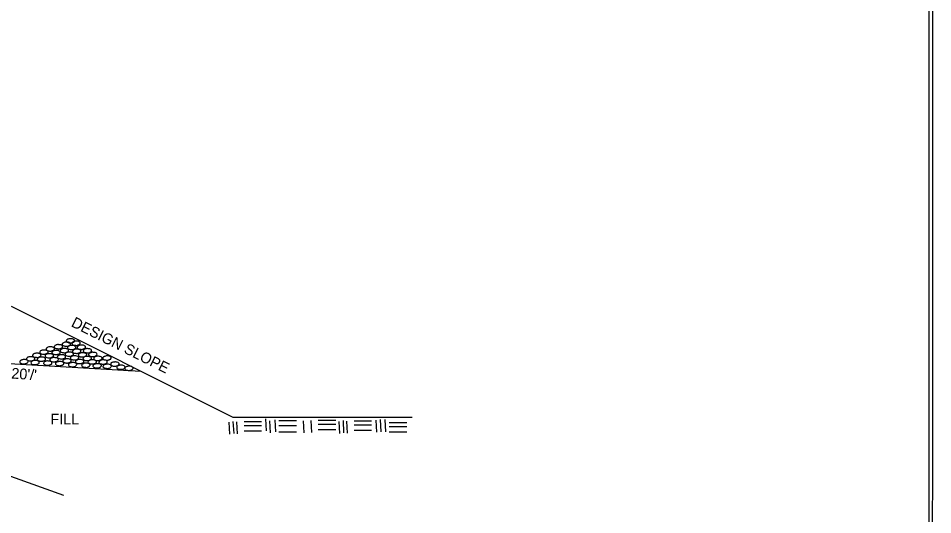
# Model space of a CAD drawing. Extents: x 714919 to 718439, y 1619644 to 1621844.
# Drawn here: x 717373 to 718397, y 1620734 to 1621289 of the extents above; entities that cross this region are included whole.
import ezdxf

# ---------------------------------------------------------------- set-up
doc = ezdxf.new("R2010")
doc.units = 0
for name, color, linetype in [('R_Annotation', 7, 'Continuous'), ('R_Border', 7, 'Continuous'), ('R_Draft', 7, 'Continuous'), ('R_No Plot', 7, 'Continuous')]:
    doc.layers.add(name, color=color, linetype=linetype)

msp = doc.modelspace()

# ---------------------------------------------------------------- linework, layer by layer
at = {"layer": 'R_Border'}
msp.add_line((718393.2, 1619722.5), (718393.1, 1621777.1), dxfattribs=at)
at = {"layer": 'R_Draft'}
for p, q in [((717614.2, 1620842.5), (717365.9, 1620966.6)), ((717203.1, 1620912.2), (717510.7, 1620894.2)), ((717076.3, 1620879.5), (717423.9, 1620755.7)), ((717814.4, 1620842.5), (717614.2, 1620842.5)), ((717650.2, 1620841), (717650.9, 1620827.5)), ((717660.5, 1620839.9), (717661.3, 1620826.4)), ((717701, 1620839.1), (717701.7, 1620825.6)), ((717728.8, 1620839.1), (717709.3, 1620839.1)), ((717737, 1620839), (717737.7, 1620825.4)), ((717773.9, 1620839.5), (717774.6, 1620825.9)), ((717778.7, 1620840), (717779.5, 1620826.5)), ((717783.8, 1620840), (717784.6, 1620826.5)), ((717609.2, 1620837.1), (717609.9, 1620823.6)), ((717613.8, 1620838.1), (717614.6, 1620824.5)), ((717617.9, 1620837.6), (717618.6, 1620824.1)), ((717645.7, 1620837.6), (717626.2, 1620837.6)), ((717645.7, 1620833.1), (717626.2, 1620833.1)), ((717654.8, 1620838.8), (717655.5, 1620825.2)), ((717685, 1620838.8), (717665.3, 1620838.8)), ((717685, 1620833), (717665.3, 1620833)), ((717692.3, 1620838.6), (717693, 1620825.1)), ((717728.8, 1620834.6), (717709.3, 1620834.6)), ((717732.3, 1620838), (717733.1, 1620824.5)), ((717741, 1620838.5), (717741.8, 1620824.9)), ((717768.9, 1620838.5), (717749.3, 1620838.5)), ((717768.9, 1620834), (717749.3, 1620834)), ((717808.4, 1620836.5), (717788.8, 1620836.5)), ((717808.4, 1620832), (717788.8, 1620832)), ((717645.7, 1620827.1), (717626.2, 1620827.1)), ((717685, 1620826.1), (717665.3, 1620826.1)), ((717728.8, 1620828.5), (717709.3, 1620828.5)), ((717768.9, 1620828), (717749.3, 1620828)), ((717808.4, 1620825.9), (717788.8, 1620825.9))]:
    msp.add_line(p, q, dxfattribs=at)
for points in [[(717409.4, 1620916.6), (717407.7, 1620916.8), (717405.7, 1620917.5), (717404.8, 1620918.3), (717404.6, 1620918.9), (717405.1, 1620919.9), (717405.7, 1620920.4), (717406.7, 1620921), (717408.3, 1620921.4), (717409.2, 1620921.4), (717410.4, 1620921.4), (717411.8, 1620921.2), (717412.9, 1620920.7), (717413.9, 1620919.8), (717414, 1620919.2), (717413.8, 1620918.3), (717413, 1620917.6), (717412.3, 1620917.4), (717411.1, 1620917), (717410.4, 1620916.7), (717409.4, 1620916.6)], [(717418.6, 1620919.2), (717416.9, 1620919.4), (717414.9, 1620920), (717413.9, 1620920.8), (717413.8, 1620921.5), (717414.3, 1620922.5), (717414.8, 1620923), (717415.9, 1620923.5), (717417.5, 1620923.9), (717418.4, 1620923.9), (717419.6, 1620923.8), (717421, 1620923.7), (717422, 1620923.3), (717423, 1620922.4), (717423.2, 1620921.8), (717422.9, 1620920.8), (717422.1, 1620920.2), (717421.4, 1620919.9), (717420.3, 1620919.5), (717419.6, 1620919.2), (717418.6, 1620919.2)], [(717427.4, 1620922), (717425.7, 1620922.2), (717423.7, 1620922.8), (717422.7, 1620923.7), (717422.6, 1620924.3), (717423.1, 1620925.2), (717423.7, 1620925.7), (717424.8, 1620926.3), (717426.3, 1620926.7), (717427.2, 1620926.7), (717428.4, 1620926.6), (717429.8, 1620926.5), (717430.9, 1620926.1), (717431.8, 1620925.2), (717432, 1620924.6), (717431.7, 1620923.6), (717431, 1620923.1), (717430.2, 1620922.7), (717429.1, 1620922.3), (717428.4, 1620922.1), (717427.4, 1620922)], [(717431.8, 1620925.7), (717430.2, 1620926), (717428.2, 1620926.5), (717427.3, 1620927.4), (717427.1, 1620928), (717427.6, 1620929), (717428.1, 1620929.5), (717429.2, 1620930.1), (717430.8, 1620930.5), (717431.7, 1620930.5), (717432.9, 1620930.4), (717434.3, 1620930.3), (717435.3, 1620929.8), (717436.4, 1620929), (717436.6, 1620928.2), (717436.3, 1620927.4), (717435.5, 1620926.7), (717434.7, 1620926.4), (717433.6, 1620926), (717432.9, 1620925.8), (717431.8, 1620925.7)], [(717433.3, 1620918.3), (717431.5, 1620918.5), (717429.6, 1620919), (717428.6, 1620920), (717428.4, 1620920.5), (717428.9, 1620921.5), (717429.5, 1620922), (717430.6, 1620922.6), (717432.2, 1620923), (717433, 1620923), (717434.3, 1620922.9), (717435.7, 1620922.8), (717436.7, 1620922.3), (717437.7, 1620921.5), (717437.9, 1620920.8), (717437.5, 1620919.9), (717436.8, 1620919.2), (717436.1, 1620919), (717435, 1620918.6), (717434.3, 1620918.3), (717433.3, 1620918.3)], [(717438.2, 1620923), (717436.6, 1620923.3), (717434.5, 1620923.7), (717433.6, 1620924.7), (717433.4, 1620925.2), (717433.9, 1620926.3), (717434.5, 1620926.7), (717435.6, 1620927.3), (717437.2, 1620927.8), (717438, 1620927.8), (717439.3, 1620927.6), (717440.7, 1620927.6), (717441.7, 1620927), (717442.7, 1620926.2), (717442.9, 1620925.5), (717442.5, 1620924.7), (717441.8, 1620924), (717441, 1620923.7), (717439.9, 1620923.3), (717439.3, 1620923.1), (717438.2, 1620923)], [(717444.2, 1620918.6), (717442.4, 1620918.8), (717440.5, 1620919.2), (717439.5, 1620920.3), (717439.3, 1620920.8), (717439.9, 1620921.8), (717440.4, 1620922.3), (717441.6, 1620922.9), (717443.2, 1620923.3), (717444, 1620923.3), (717445.2, 1620923.3), (717446.6, 1620923.2), (717447.7, 1620922.6), (717448.6, 1620921.8), (717448.8, 1620921.1), (717448.5, 1620920.2), (717447.7, 1620919.6), (717447, 1620919.2), (717445.9, 1620918.9), (717445.2, 1620918.7), (717444.2, 1620918.6)], [(717394.2, 1620909.6), (717392.5, 1620909.8), (717390.6, 1620910.3), (717389.6, 1620911.3), (717389.5, 1620911.8), (717389.9, 1620912.8), (717390.4, 1620913.3), (717391.5, 1620913.8), (717393.2, 1620914.3), (717394, 1620914.3), (717395.2, 1620914.2), (717396.6, 1620914.1), (717397.7, 1620913.6), (717398.7, 1620912.8), (717398.9, 1620912.1), (717398.6, 1620911.2), (717397.8, 1620910.6), (717397.1, 1620910.3), (717395.9, 1620909.8), (717395.2, 1620909.6), (717394.2, 1620909.6)], [(717402.2, 1620913.2), (717400.5, 1620913.3), (717398.5, 1620913.9), (717397.5, 1620914.8), (717397.4, 1620915.4), (717397.8, 1620916.4), (717398.5, 1620916.8), (717399.6, 1620917.5), (717401.2, 1620917.8), (717402, 1620917.8), (717403.2, 1620917.8), (717404.6, 1620917.6), (717405.7, 1620917.2), (717406.7, 1620916.3), (717406.8, 1620915.7), (717406.5, 1620914.7), (717405.7, 1620914.2), (717405, 1620913.8), (717404, 1620913.5), (717403.3, 1620913.3), (717402.2, 1620913.2)], [(717408.2, 1620909), (717406.5, 1620909.2), (717404.5, 1620909.8), (717403.6, 1620910.7), (717403.4, 1620911.3), (717403.9, 1620912.3), (717404.4, 1620912.8), (717405.6, 1620913.4), (717407.2, 1620913.7), (717408, 1620913.7), (717409.3, 1620913.7), (717410.6, 1620913.6), (717411.7, 1620913.1), (717412.7, 1620912.2), (717412.8, 1620911.6), (717412.5, 1620910.6), (717411.8, 1620910.1), (717411, 1620909.8), (717409.9, 1620909.3), (717409.3, 1620909.1), (717408.2, 1620909)], [(717415.8, 1620912.7), (717414.1, 1620912.9), (717412.2, 1620913.5), (717411.2, 1620914.4), (717411, 1620914.9), (717411.6, 1620916), (717412.1, 1620916.5), (717413.2, 1620917.1), (717414.8, 1620917.5), (717415.6, 1620917.5), (717416.9, 1620917.5), (717418.3, 1620917.3), (717419.3, 1620916.7), (717420.3, 1620915.9), (717420.5, 1620915.3), (717420.2, 1620914.4), (717419.4, 1620913.7), (717418.7, 1620913.4), (717417.5, 1620913.1), (717416.9, 1620912.8), (717415.8, 1620912.7)], [(717421.9, 1620907.8), (717420.2, 1620908), (717418.2, 1620908.6), (717417.2, 1620909.4), (717417.1, 1620910), (717417.6, 1620911), (717418.2, 1620911.6), (717419.2, 1620912.1), (717420.8, 1620912.5), (717421.6, 1620912.5), (717422.9, 1620912.5), (717424.3, 1620912.3), (717425.4, 1620911.8), (717426.4, 1620910.9), (717426.5, 1620910.4), (717426.2, 1620909.4), (717425.5, 1620908.8), (717424.7, 1620908.5), (717423.6, 1620908.1), (717422.9, 1620907.9), (717421.9, 1620907.8)], [(717425.3, 1620914.8), (717423.6, 1620915), (717421.5, 1620915.6), (717420.5, 1620916.5), (717420.4, 1620917.1), (717420.9, 1620918), (717421.5, 1620918.6), (717422.7, 1620919.2), (717424.2, 1620919.5), (717425, 1620919.5), (717426.3, 1620919.5), (717427.6, 1620919.3), (717428.8, 1620918.9), (717429.7, 1620918), (717429.8, 1620917.4), (717429.5, 1620916.4), (717428.8, 1620915.9), (717428.1, 1620915.5), (717427, 1620915.2), (717426.3, 1620914.9), (717425.3, 1620914.8)], [(717430.6, 1620910.9), (717428.9, 1620911), (717427, 1620911.6), (717426, 1620912.5), (717425.9, 1620913.1), (717426.3, 1620914.1), (717426.8, 1620914.6), (717428, 1620915.2), (717429.5, 1620915.6), (717430.4, 1620915.6), (717431.6, 1620915.5), (717433, 1620915.4), (717434.1, 1620914.9), (717435.1, 1620914), (717435.2, 1620913.4), (717435, 1620912.5), (717434.2, 1620911.9), (717433.5, 1620911.6), (717432.3, 1620911.1), (717431.6, 1620910.9), (717430.6, 1620910.9)], [(717436.4, 1620911.4), (717438, 1620911.4), (717440.1, 1620910.7), (717441, 1620909.8), (717441.2, 1620909.2), (717440.6, 1620908.2), (717440.1, 1620907.7), (717439, 1620907.2), (717437.4, 1620906.8), (717436.5, 1620906.7), (717435.3, 1620906.9), (717433.9, 1620907.1), (717432.9, 1620907.4), (717431.9, 1620908.3), (717431.7, 1620908.9), (717432, 1620909.8), (717432.8, 1620910.4), (717433.5, 1620910.9), (717434.6, 1620911.3), (717435.3, 1620911.4), (717436.4, 1620911.4)], [(717438.8, 1620914), (717437.2, 1620914.3), (717435.2, 1620914.7), (717434.2, 1620915.7), (717434.1, 1620916.3), (717434.6, 1620917.3), (717435.1, 1620917.7), (717436.3, 1620918.4), (717437.8, 1620918.8), (717438.7, 1620918.8), (717439.9, 1620918.7), (717441.3, 1620918.6), (717442.3, 1620918.1), (717443.4, 1620917.3), (717443.5, 1620916.6), (717443.2, 1620915.7), (717442.4, 1620915.1), (717441.7, 1620914.7), (717440.6, 1620914.4), (717439.9, 1620914.1), (717438.8, 1620914)], [(717445.2, 1620914.8), (717447, 1620914.7), (717449, 1620914.1), (717450, 1620913.2), (717450.1, 1620912.6), (717449.6, 1620911.6), (717449, 1620911.2), (717447.9, 1620910.5), (717446.3, 1620910.2), (717445.5, 1620910.2), (717444.2, 1620910.3), (717442.8, 1620910.3), (717441.8, 1620910.8), (717440.8, 1620911.7), (717440.7, 1620912.3), (717441, 1620913.2), (717441.8, 1620913.8), (717442.4, 1620914.2), (717443.6, 1620914.6), (717444.2, 1620914.8), (717445.2, 1620914.8)], [(717450.4, 1620910.8), (717452.1, 1620910.6), (717454.1, 1620910.1), (717455.2, 1620909.1), (717455.3, 1620908.5), (717454.8, 1620907.5), (717454.2, 1620907.1), (717453, 1620906.6), (717451.4, 1620906), (717450.6, 1620906), (717449.3, 1620906.2), (717448, 1620906.3), (717447, 1620906.8), (717446, 1620907.6), (717445.9, 1620908.2), (717446.2, 1620909.1), (717446.8, 1620909.8), (717447.5, 1620910.2), (717448.6, 1620910.6), (717449.4, 1620910.7), (717450.4, 1620910.8)], [(717450.8, 1620919.5), (717452.4, 1620919.2), (717454.4, 1620918.8), (717455.5, 1620917.8), (717455.6, 1620917.3), (717455.1, 1620916.2), (717454.5, 1620915.8), (717453.4, 1620915.1), (717451.8, 1620914.7), (717451, 1620914.7), (717449.8, 1620914.9), (717448.3, 1620915), (717447.3, 1620915.4), (717446.3, 1620916.3), (717446.2, 1620917), (717446.5, 1620917.8), (717447.2, 1620918.5), (717447.9, 1620918.9), (717449, 1620919.2), (717449.7, 1620919.4), (717450.8, 1620919.5)], [(717456.8, 1620915.3), (717458.5, 1620915.1), (717460.5, 1620914.6), (717461.5, 1620913.6), (717461.7, 1620913.1), (717461.1, 1620912), (717460.6, 1620911.6), (717459.4, 1620910.9), (717457.9, 1620910.6), (717457, 1620910.6), (717455.7, 1620910.6), (717454.3, 1620910.7), (717453.3, 1620911.3), (717452.3, 1620912.1), (717452.2, 1620912.8), (717452.5, 1620913.6), (717453.2, 1620914.3), (717454, 1620914.6), (717455.1, 1620915), (717455.7, 1620915.2), (717456.8, 1620915.3)], [(717462.5, 1620910.9), (717464.2, 1620910.7), (717466.1, 1620910.2), (717467.2, 1620909.3), (717467.3, 1620908.7), (717466.7, 1620907.7), (717466.2, 1620907.3), (717465.1, 1620906.7), (717463.5, 1620906.2), (717462.6, 1620906.2), (717461.4, 1620906.3), (717460, 1620906.4), (717458.9, 1620906.9), (717458, 1620907.8), (717457.9, 1620908.4), (717458.1, 1620909.3), (717458.9, 1620909.9), (717459.6, 1620910.3), (717460.7, 1620910.7), (717461.5, 1620910.9), (717462.5, 1620910.9)], [(717472.8, 1620906.6), (717471.1, 1620906.8), (717469.2, 1620907.3), (717468.2, 1620908.2), (717468.1, 1620908.8), (717468.6, 1620909.8), (717469.1, 1620910.3), (717470.2, 1620910.8), (717471.8, 1620911.3), (717472.7, 1620911.3), (717473.9, 1620911.2), (717475.3, 1620911.1), (717476.3, 1620910.6), (717477.3, 1620909.7), (717477.5, 1620909), (717477.2, 1620908.2), (717476.5, 1620907.5), (717475.7, 1620907.3), (717474.5, 1620906.8), (717473.9, 1620906.6), (717472.8, 1620906.6)], [(717379.8, 1620902.5), (717378.2, 1620902.6), (717376.3, 1620903.1), (717375.3, 1620904.1), (717375.1, 1620904.6), (717375.7, 1620905.7), (717376.1, 1620906.1), (717377.3, 1620906.8), (717378.9, 1620907.1), (717379.7, 1620907.1), (717381, 1620907.1), (717382.4, 1620907), (717383.5, 1620906.5), (717384.4, 1620905.6), (717384.6, 1620904.9), (717384.2, 1620904.1), (717383.6, 1620903.4), (717382.7, 1620903.1), (717381.6, 1620902.7), (717381, 1620902.5), (717379.8, 1620902.5)], [(717387.2, 1620905.7), (717385.5, 1620905.8), (717383.6, 1620906.4), (717382.6, 1620907.3), (717382.5, 1620907.9), (717383, 1620908.9), (717383.5, 1620909.4), (717384.6, 1620910), (717386.2, 1620910.4), (717387, 1620910.4), (717388.3, 1620910.3), (717389.7, 1620910.2), (717390.7, 1620909.7), (717391.8, 1620908.8), (717391.9, 1620908.2), (717391.6, 1620907.3), (717390.9, 1620906.7), (717390.1, 1620906.3), (717388.9, 1620905.9), (717388.3, 1620905.7), (717387.2, 1620905.7)], [(717392.3, 1620901.5), (717390.6, 1620901.6), (717388.6, 1620902.2), (717387.7, 1620903.1), (717387.5, 1620903.7), (717388.1, 1620904.7), (717388.5, 1620905.2), (717389.7, 1620905.8), (717391.3, 1620906.2), (717392.1, 1620906.2), (717393.4, 1620906.1), (717394.7, 1620906), (717395.8, 1620905.5), (717396.8, 1620904.6), (717397, 1620904), (717396.7, 1620903), (717395.9, 1620902.5), (717395.2, 1620902.1), (717394, 1620901.7), (717393.4, 1620901.5), (717392.3, 1620901.5)], [(717399.4, 1620905.3), (717397.7, 1620905.5), (717395.8, 1620906), (717394.8, 1620907), (717394.7, 1620907.5), (717395.2, 1620908.5), (717395.7, 1620909), (717396.8, 1620909.6), (717398.4, 1620910), (717399.2, 1620910), (717400.5, 1620909.9), (717401.8, 1620909.8), (717402.9, 1620909.3), (717403.9, 1620908.5), (717404.1, 1620907.8), (717403.8, 1620906.9), (717403, 1620906.3), (717402.3, 1620905.9), (717401.2, 1620905.6), (717400.5, 1620905.3), (717399.4, 1620905.3)], [(717406.5, 1620900.9), (717404.8, 1620901.1), (717402.9, 1620901.6), (717401.9, 1620902.6), (717401.8, 1620903.1), (717402.3, 1620904.2), (717402.8, 1620904.6), (717403.9, 1620905.2), (717405.5, 1620905.6), (717406.3, 1620905.6), (717407.6, 1620905.5), (717409, 1620905.4), (717410, 1620904.9), (717411, 1620904.1), (717411.2, 1620903.4), (717410.9, 1620902.5), (717410.1, 1620901.9), (717409.4, 1620901.6), (717408.2, 1620901.2), (717407.6, 1620900.9), (717406.5, 1620900.9)], [(717413.7, 1620904.6), (717412, 1620904.8), (717410, 1620905.4), (717409, 1620906.3), (717408.8, 1620906.9), (717409.3, 1620907.9), (717409.9, 1620908.4), (717411, 1620909), (717412.6, 1620909.4), (717413.5, 1620909.4), (717414.7, 1620909.3), (717416.1, 1620909.2), (717417.2, 1620908.7), (717418.1, 1620907.8), (717418.3, 1620907.2), (717417.9, 1620906.3), (717417.2, 1620905.7), (717416.5, 1620905.4), (717415.4, 1620905), (717414.7, 1620904.8), (717413.7, 1620904.6)], [(717419.8, 1620905.1), (717421.4, 1620905), (717423.4, 1620904.3), (717424.4, 1620903.4), (717424.6, 1620902.8), (717424.1, 1620901.8), (717423.4, 1620901.4), (717422.4, 1620900.8), (717420.7, 1620900.4), (717419.9, 1620900.3), (717418.7, 1620900.4), (717417.3, 1620900.7), (717416.3, 1620901.1), (717415.3, 1620901.9), (717415.1, 1620902.6), (717415.4, 1620903.4), (717416.2, 1620904.1), (717416.9, 1620904.5), (717418, 1620904.8), (717418.7, 1620905), (717419.8, 1620905.1)], [(717428, 1620908), (717429.7, 1620908), (717431.7, 1620907.3), (717432.7, 1620906.4), (717432.8, 1620905.8), (717432.3, 1620904.8), (717431.7, 1620904.3), (717430.6, 1620903.8), (717429, 1620903.4), (717428.2, 1620903.3), (717427, 1620903.4), (717425.6, 1620903.7), (717424.5, 1620904.1), (717423.6, 1620904.8), (717423.4, 1620905.5), (717423.7, 1620906.4), (717424.5, 1620907), (717425.2, 1620907.5), (717426.3, 1620907.8), (717427, 1620908), (717428, 1620908)], [(717434.2, 1620904), (717435.9, 1620903.8), (717437.8, 1620903.1), (717438.8, 1620902.3), (717439, 1620901.7), (717438.4, 1620900.7), (717437.9, 1620900.2), (717436.8, 1620899.6), (717435.2, 1620899.2), (717434.4, 1620899.2), (717433.1, 1620899.2), (717431.7, 1620899.4), (717430.6, 1620899.9), (717429.7, 1620900.8), (717429.5, 1620901.4), (717429.8, 1620902.3), (717430.6, 1620902.9), (717431.3, 1620903.2), (717432.5, 1620903.6), (717433.1, 1620903.8), (717434.2, 1620904)], [(717442.1, 1620907.4), (717443.8, 1620907.2), (717445.8, 1620906.6), (717446.8, 1620905.7), (717447, 1620905.2), (717446.5, 1620904.2), (717445.9, 1620903.7), (717444.7, 1620903), (717443.2, 1620902.7), (717442.3, 1620902.7), (717441.1, 1620902.7), (717439.7, 1620902.9), (717438.7, 1620903.3), (717437.7, 1620904.2), (717437.5, 1620904.8), (717437.9, 1620905.8), (717438.6, 1620906.4), (717439.3, 1620906.7), (717440.4, 1620907.1), (717441, 1620907.3), (717442.1, 1620907.4)], [(717449.1, 1620903.2), (717450.8, 1620903), (717452.8, 1620902.6), (717453.7, 1620901.6), (717453.9, 1620901), (717453.3, 1620900), (717452.8, 1620899.6), (717451.7, 1620899), (717450.1, 1620898.5), (717449.3, 1620898.5), (717448.1, 1620898.6), (717446.7, 1620898.8), (717445.6, 1620899.2), (717444.6, 1620900.1), (717444.4, 1620900.7), (717444.7, 1620901.6), (717445.5, 1620902.3), (717446.3, 1620902.6), (717447.4, 1620903), (717448.1, 1620903.2), (717449.1, 1620903.2)], [(717456.2, 1620907), (717457.9, 1620906.8), (717459.8, 1620906.3), (717460.8, 1620905.3), (717461, 1620904.8), (717460.5, 1620903.8), (717459.9, 1620903.2), (717458.8, 1620902.7), (717457.2, 1620902.3), (717456.4, 1620902.3), (717455.1, 1620902.4), (717453.7, 1620902.5), (717452.7, 1620903), (717451.6, 1620903.8), (717451.5, 1620904.4), (717451.8, 1620905.4), (717452.6, 1620905.9), (717453.3, 1620906.3), (717454.4, 1620906.8), (717455.1, 1620907), (717456.2, 1620907)], [(717461.7, 1620902.6), (717463.5, 1620902.5), (717465.4, 1620901.8), (717466.3, 1620900.9), (717466.5, 1620900.3), (717466, 1620899.3), (717465.5, 1620898.9), (717464.4, 1620898.4), (717462.8, 1620897.8), (717462, 1620897.8), (717460.7, 1620898), (717459.4, 1620898.1), (717458.2, 1620898.5), (717457.2, 1620899.4), (717457, 1620900.1), (717457.4, 1620901), (717458.1, 1620901.6), (717458.9, 1620902), (717460, 1620902.4), (717460.7, 1620902.6), (717461.7, 1620902.6)], [(717468.4, 1620906.8), (717470, 1620906.7), (717472.1, 1620906), (717473, 1620905.1), (717473.1, 1620904.5), (717472.7, 1620903.5), (717472.2, 1620903), (717471, 1620902.6), (717469.4, 1620902), (717468.6, 1620902), (717467.3, 1620902.1), (717466, 1620902.4), (717464.9, 1620902.7), (717463.9, 1620903.6), (717463.7, 1620904.3), (717464.1, 1620905.2), (717464.8, 1620905.8), (717465.6, 1620906.1), (717466.6, 1620906.6), (717467.3, 1620906.8), (717468.4, 1620906.8)], [(717473, 1620901.9), (717474.6, 1620901.9), (717476.6, 1620901.3), (717477.5, 1620900.4), (717477.7, 1620899.9), (717477.2, 1620898.7), (717476.7, 1620898.3), (717475.6, 1620897.7), (717474, 1620897.3), (717473.1, 1620897.2), (717471.9, 1620897.4), (717470.5, 1620897.6), (717469.4, 1620898), (717468.4, 1620898.8), (717468.2, 1620899.4), (717468.6, 1620900.3), (717469.3, 1620901), (717470, 1620901.5), (717471.2, 1620901.7), (717471.9, 1620901.9), (717473, 1620901.9)], [(717481.5, 1620904.5), (717483.2, 1620904.4), (717485.2, 1620903.8), (717486.2, 1620903), (717486.3, 1620902.5), (717485.8, 1620901.3), (717485.3, 1620900.8), (717484.1, 1620900.3), (717482.6, 1620899.9), (717481.8, 1620899.9), (717480.5, 1620899.9), (717479.1, 1620900.1), (717478.1, 1620900.6), (717477.1, 1620901.4), (717476.9, 1620902), (717477.2, 1620903), (717478, 1620903.7), (717478.7, 1620904), (717479.8, 1620904.3), (717480.5, 1620904.4), (717481.5, 1620904.5)], [(717488.3, 1620901), (717490, 1620900.8), (717491.9, 1620900.2), (717492.9, 1620899.3), (717493, 1620898.8), (717492.6, 1620897.7), (717492, 1620897.2), (717490.9, 1620896.6), (717489.3, 1620896.3), (717488.5, 1620896.3), (717487.2, 1620896.3), (717485.9, 1620896.5), (717484.8, 1620897), (717483.8, 1620897.8), (717483.6, 1620898.5), (717483.9, 1620899.4), (717484.7, 1620900), (717485.4, 1620900.3), (717486.5, 1620900.7), (717487.3, 1620900.9), (717488.3, 1620901)], [(717497.4, 1620895.1), (717495.7, 1620895.2), (717493.8, 1620895.8), (717492.8, 1620896.7), (717492.7, 1620897.3), (717493.2, 1620898.4), (717493.6, 1620898.8), (717494.8, 1620899.3), (717496.4, 1620899.8), (717497.2, 1620899.8), (717498.5, 1620899.7), (717499.9, 1620899.6), (717500.9, 1620899.1), (717501.9, 1620898.3), (717502, 1620897.6), (717501.8, 1620896.7), (717501.1, 1620896.1), (717500.3, 1620895.7), (717499.1, 1620895.3), (717498.5, 1620895.1), (717497.4, 1620895.1)]]:
    msp.add_spline(points, degree=3, dxfattribs=at)
at = {"layer": 'R_No Plot'}
msp.add_lwpolyline([(715227.2, 1619717.3), (718397.1, 1619717.4), (718397.2, 1621782.5), (715227.1, 1621782.3)], close=True, dxfattribs=at)

# ---------------------------------------------------------------- texts
at = {"layer": 'R_Annotation'}
for s, rotation, p in [('DESIGN SLOPE', 333.435, (717431.8, 1620944.7)), ("0.020'/'", 355.6232, (717343.1, 1620887.8))]:
    msp.add_text(s, height=12, rotation=rotation, dxfattribs=at).set_placement(p)
msp.add_text('FILL', height=12, dxfattribs=at).set_placement((717409.5, 1620834.7))

doc.saveas('drawing.dxf')
